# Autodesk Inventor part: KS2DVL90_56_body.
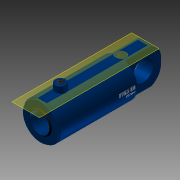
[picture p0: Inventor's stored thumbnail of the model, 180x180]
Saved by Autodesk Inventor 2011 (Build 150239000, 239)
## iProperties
Created: 2010-11
Document SubType Name: Modeling
Designer: TB
Mass: 405.061 g
Surface Area: 916.939 cm^2
Volume: 405.061 cm^3
Density: 1 g/cm^3
Author: TB
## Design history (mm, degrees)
sketch "Sketch2"
  geometry: L1 (-35, -3)-(-35, 3); L2 (-35, -9)-(-35, 9); L3 (-35, 0)-(-35, 52.5); L4 (-35, 52.5)-(-249, 52.5); L5 (-249, 52.5)-(-249, 50); L6 (-249, 50)-(-254, 50); L7 (-254, 50)-(-254, 32); L8 (-254, 32)-(-257, 29); L9 (-257, 29)-(-257, 28); L10 (-257, 28)-(-194, 28); L11 (-194, 28)-(-194, 45); L12 (-194, 45)-(-55, 45); L13 (-55, 45)-(-55, 0); L14 (-55, 0)-(-35, 0); L15 (-55, 0)-(-148.421, 0); L16 (-35, 9)-(-32, 12) reference; L17 (-32, 12)-(-35, 12) reference; L18 (-35, 12)-(-35, 9) reference; L19 (-32, 12)-(-35, 9) reference; L20 (-32, 12)-(-35, 12) reference; L21 (-35, 9)-(-35, 12) reference; L22 (-35, 9)-(-32, 12) reference; 1 further point
  constraints: 44 end point, 8 perpendicular, 6 parallel, 5 collinear, 2 horizontal, 2 vertical, 1 coincident, 1 midpoint, 1 point on line, 10 other
  dimensions: "DiaY" = 105 diameter of L4 L15; "DiaI" = 90 diameter of L12 L15; "d4" = 1 distance of L8.end L9.end; "d5" = 45 deg angle of L10 L8; "d6" = 3 distance between parallel lines of L7 L9; "DiaStang" = 56 diameter of L10 L15; "RindDia" = 100 diameter of L6 L15; "RingLengde" = 5 distance of L5.end L6.end; "RingTykk" = 60 distance between parallel lines of L11 L7; "KroppLengde" = 219 distance between parallel lines of L7 L3 (derived); "BunnTykkelse" = 20 distance between parallel lines of L13 L3
revolve "Kropp" sketch "Sketch2" stored, may be unused: angle "d13" = 90 deg
sketch "Sketch3"
  geometry: L1 (-55, -45)-(-55, 45) reference; L2 (-55, 0.01)-(-155, 0.01); L3 (-155, -0.01)-(-55, -0.01); A1 r 0.01 centre (-155, 0) between (-155, 0.01) and (-155, -0.01); A2 r 0.01 centre (-55, 0) between (-55, -0.01) and (-55, 0.01); 2 further points
  constraints: 4 end point, 4 point on circle, 4 tangent, 2 centre point, 1 coincident, 1 midpoint, 1 parallel, 1 perpendicular
  dimensions: "d17" = 0.01 radius of A2; "d18" = 100 distance of L2.start L2.end (= Slaglengde)
feature "BaneTransitionalConstraint" sketch "Sketch3" dims "d19" = 2, "d20" = 0
sketch "Sketch6"
  geometry: L1 (-73.5, 0)-(73.5, 0) reference; L2 (12.46, 51)-(-11.843, 51); L3 (52.5, 0)-(52.5, 31.248); L4 (-52.5, 0)-(-52.5, -18.451); A1 r 52.5 centre (0, 0) between (-52.5, 0) and (52.5, 0) reference; 2 further points
  constraints: 6 end point, 2 point on circle, 2 vertical, 2 other
  dimensions: "d30" = 51 distance from line of point (0, 0) L2 (computed from DiaY); "d31" = 0 deg angle of L1 L2 (computed from Vinkel_Plussport); "d37" = 90 deg angle of L2 L3; "d38" = 90 deg angle of L2 L4
  node "Projected Loop3"
workplane "Work Plane5"
sketch "Sketch7"
  geometry: L1 (12.46, -308.4)-(12.46, 51.4) reference; L2 (-19.633, -35)-(38.367, -35) reference; C1 r 15 at (12.46, -52.5); 1 further point
  constraints: 1 centre point, 1 point on line
  dimensions: "PortDia" = 30 diameter of C1
extrude "Extrusion2" cut sketch "Sketch7" stored distance "d34" = 1.5; taper "d35" = 0 deg
workplane "Work Plane7"
sketch "Sketch4"
  geometry: L1 (-16.68, -40)-(-16.68, -78.777); L2 (-16.68, -78.777)-(16.68, -78.777); L3 (16.68, -78.777)-(16.68, -40); L4 (16.68, -40)-(-16.68, -40); L5 (-40.643, -40)-(0, -40); L6 (-29, -35)-(29, -35); L7 (0, -35)-(0, -40); 2 further points
  constraints: 6 end point, 2 midpoint, 2 other
  dimensions: "d40" = 5 distance of L7.start L5.end
emboss "Emboss1" sketch "Sketch4" dims "d4" = 1, "d5" = 45 deg, "d6" = 3, "d22" = 0.2, "d23" = 0, "DiaI" = 90, "DiaY" = 105, "RindDia" = 100, "DiaStang" = 56, "RingTykk" = 60, "RingLengde" = 5, "KroppLengde" = 219 (derived), "BunnTykkelse" = 20
workplane "Work Plane8"
sketch "Sketch8"
  geometry: L1 (-29, -35)-(29, -35); L2 (0, -35)-(0, -40); L3 (-5.906, -110.587)-(-5.906, -40); L4 (-5.906, -40)-(5.906, -40); L5 (5.906, -40)-(5.906, -110.587); L6 (5.906, -110.587)-(-5.906, -110.587); L7 (52.5, -35)-(-52.5, -35); L8 (52.5, -35)-(-52.5, -35) reference; 3 further points
  constraints: 6 end point, 4 midpoint, 2 other
  dimensions: "d42" = 5 distance of L2.start L2.end
emboss "Emboss2" sketch "Sketch8" dims "d4" = 1, "d5" = 45 deg, "d6" = 3, "d43" = 0.2, "d44" = 0, "DiaI" = 90, "DiaY" = 105, "RindDia" = 100, "DiaStang" = 56, "RingTykk" = 60, "RingLengde" = 5, "KroppLengde" = 219 (derived), "BunnTykkelse" = 20
sketch "Sketch9"
  geometry: A1 r 12.5 centre (9.367, -52.5) between (0, -60.776) and (18.735, -60.776) reference; 1 further point
hole "Hole1" sketch "Sketch9" at (9.367, -52.5) diameter "d45" = 14.95; stored, may be unused: countersink angle "d49" = 82 deg, drill point angle "d51" = 118 deg; dims "d46" = 6, "d47" = 3.023, "d48" = 2, "DiaInvPluss" = 15
workplane "Work Plane9"
sketch "Sketch10"
  geometry: L1 (-73.5, 0)-(73.5, 0) reference; L2 (0, 52.5)-(13.136, 52.5); L3 (0, 52.5)-(0, 31.79); L4 (15, 50.312)-(15, 70); L5 (15, 70)-(0, 70); L6 (0, 70)-(0, 52.5); L7 (0, 52.5)-(15, 50.312); C1 r 52.5 at (0, 0) reference; A1 r 52.5 centre (0, 0) between (0, 52.5) and (15, 50.312); 1 further point
  constraints: 12 end point, 4 perpendicular, 2 concentric, 2 point on circle, 1 centre point, 1 point on line, 1 tangent
  dimensions: "d53" = 0 deg angle of L1 L2 (computed from Vinkel_Minusport); "DiaUtvStussMinus" = 30 diameter of L4 L3; "HøydeStussMinuss" = 17.5 distance between parallel lines of L2 L5
revolve "Revolution2" sketch "Sketch10" stored, may be unused: angle "d56" = 90 deg
hole "Hole2" diameter "d59" = 18.631; stored, may be unused: countersink angle "d63" = 82 deg, drill point angle "d65" = 118 deg; dims "d57" = 10, "d58" = 10, "d60" = 6, "d61" = 3.023, "d62" = 2, "DiaInvStussMinus" = 18
fillet "Fillet1" dims "d66" = 2
sketch "Sketch15"
  geometry: L1 (19, -48.941)-(19, 48.941); L2 (-19, -48.941)-(-19, 48.941); L3 (0, 73.5)-(0, -73.5) reference; A1 r 52.5 centre (0, 0) between (19, -48.941) and (-19, -48.941) reference; A2 r 52.5 centre (0, 0) between (19, 48.941) and (-19, 48.941); A3 r 52.5 centre (0, 0) between (-19, -48.941) and (19, -48.941)
  constraints: 8 point on circle, 4 end point, 4 point on line, 2 centre point, 2 concentric, 2 parallel, 1 coincident
  dimensions: "EyeBunnTykk" = 19 distance from line of L1 A1.centre; "EyeBunnTykk2" = 19 distance from line of A1.centre L2
extrude "Extrusion6" join sketch "Sketch15" taper "d98" = 0 deg; distance "LengdeEyeMinussBunntykk" = 100
sketch "Sketch16"
  geometry: L1 (-249, 52.5)-(65, 52.5) reference; L2 (-249, -52.5)-(65, -52.5) reference; L3 (-249, 52.5)-(65, 52.5) reference; L4 (65, 52.5)-(65, 48.941) reference; L5 (65, -48.941)-(65, 48.941) reference; L6 (-313.643, 0)-(138.86, 0) reference; L7 (20.5, 52.5)-(65, 52.5); L8 (65, 52.5)-(65, 8); A1 r 44.5 centre (20.5, 8) between (65, 8) and (20.5, 52.5); 6 further points; 2 other entities
  constraints: 4 end point, 4 tangent, 2 point on circle, 2 point on line, 1 centre point, 1 collinear, 1 perpendicular, 2 other
  dimensions: "d137" = 8 distance from line of L8.end L6
extrude "Extrusion7" cut sketch "Sketch16" taper "d102" = 0 deg; stored distance "ExtruEyeBunn" = 38
mirror "Mirror1"
sketch "Sketch20"
  geometry: L1 (-249, 52.5)-(65, 52.5) reference; L2 (65, -48.941)-(65, 48.941) reference; L3 (65, 52.5)-(65, 48.941) reference; L4 (-312.808, 0)-(133.847, 0) reference; L5 (-35, -48.941)-(-35, 48.941) reference; L6 (-35, 0)-(11, 0); L7 (11, 0)-(11, 20.918); L8 (34.022, 49.669)-(28.1, 51.873); A1 r 30 centre (22, 22.5) between (28.1, 51.873) and (22, 52.5); A2 r 54.745 centre (11, 0) between (65, 9) and (34.022, 49.669); 1 further point
  constraints: 6 end point, 4 point on circle, 3 point on line, 2 centre point, 1 coincident, 1 midpoint, 1 perpendicular, 1 tangent
  dimensions: "d147" = 46 distance of L6.start L6.end; "d150" = 30 radius of A1; "d157" = 9 distance from line of L4 A2.start; "d158" = 20.4178 deg angle of L1 L8
extrude "Extrusion10" cut sketch "Sketch20" stored distance "d144" = 10; taper "d145" = 0 deg
mirror "Mirror2"
sketch "Sketch17"
  geometry: L1 (97.883, 0)-(0, 0) reference; L2 (48.941, -286.4)-(48.941, 164.4) reference; C1 r 28.5 at (48.941, 50); 1 further point
  constraints: 1 centre point, 1 point on line
  dimensions: "DiaHullEyeBunn" = 57 diameter of C1; "d125" = 50 distance from line of C1.centre L1
extrude "Extrusion8" cut sketch "Sketch17" taper "d105" = 0 deg; distance "ExtruHullEye" = 38
pattern_circular "Circular Pattern1 Only Subsea" dims "d108" = 180 deg (derived)
workplane "Work Plane11"
sketch "Sketch18"
  geometry: L1 (0, -66)-(0, 11) reference; L2 (45, -55)-(-45, -55) reference; L3 (45, -55)-(-45, -55) reference; C1 r 15 at (0, -29); 1 further point
  constraints: 1 centre point
  dimensions: "DiaForsenkPlussPort" = 30 diameter of C1; "PlassPlussport" = 26 distance from line of L2 C1.centre
extrude "Extrusion9" cut sketch "Sketch18" stored distance "d113" = 10; taper "d114" = 0 deg
sketch "Sketch19"
  geometry: 10 further points
  constraints: 1 other
hole "Hole3" sketch "Sketch19" at (0, -29) diameter "d115" = 18.631; stored, may be unused: countersink angle "d119" = 90 deg, drill point angle "d121" = 118 deg; dims "d116" = 6, "d117" = 4, "d118" = 2, "d120" = 14.5
pattern_circular "Circular Pattern2 Only Subsea" dims angle "d123" = 360 deg
body "Solid1"
chamfer "Chamfer" distance "Chamfer" = 1; stored, may be unused: second distance "d15" = 2, angle "d16" = 45 deg
node "Projected Loop2"
body "Srf1"
node "Projected Loop10"
other parameters: "Slaglengde" = 100, "Forlengelse_rør" = 0, "Vinkel_Plussport" = 0 [user parameter; used in 1 equation term], "Vinkel_Minusport" = 0, "d32" = 90 deg, "d39" = 90 deg, "d41" = 90 deg, "PortMinusPlass" = -56, "Minusport2" = 180 deg, "ForsenkningPlussPort" = 50.7 (derived)
